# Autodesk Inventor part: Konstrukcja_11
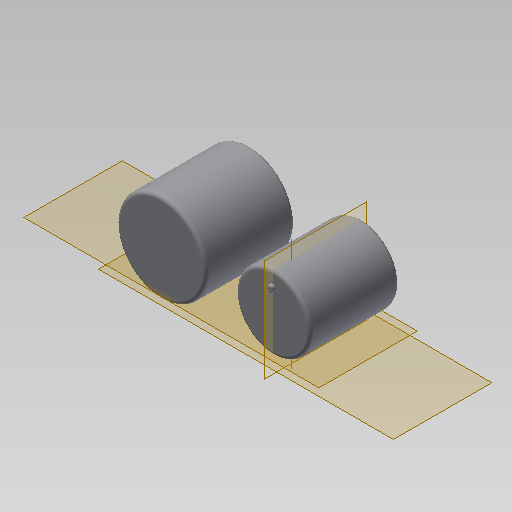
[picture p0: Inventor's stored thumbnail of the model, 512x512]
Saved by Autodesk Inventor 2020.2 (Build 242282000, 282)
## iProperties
Created: 2014-09
Part Number: Konstrukcja_11
Material: Ogólny
Document SubType Name: Modeling
Designer: F.Stasiak
Density: 1 g/cm^3
Appearance: Domyślna
Catalog Web Link: www.expertbooks.pl
Manager: www.cadconsulting.pl
Company: Fabian Stasiak CAD Consulting
Author: F.Stasiak
Subject: Zbiór ćwiczeń. Autodesk Inventor 2020. Kurs Professional
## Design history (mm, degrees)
sketch "Szkic1"
  geometry: L1 (0, 0)-(1500, 0); C1 r 600 at (0, 0); C2 r 500 at (1500, 0); 1 further point
  constraints: 2 centre point, 2 end point, 1 coincident, 1 horizontal
  dimensions: "d0" = 1200 diameter of C1; "d1" = 1000 diameter of C2; "d2" = 1500 distance of L1.start L1.end
extrude "Wyciągnięcie proste1" new body sketch "Szkic1" distance "d3" = 1200; taper "d4" = 0 deg
node "Płaszczyzna konstrukcyjna1"
sketch "Szkic2"
  geometry: C1 r 40 at (0, 350); C2 r 40 at (0, 900); 1 further point
  constraints: 2 centre point, 1 equal radius, 1 vertical alignment
  dimensions: "d5" = 80 diameter of C1; "d6" = 350 distance of point (0, 0) C1.centre; "d9" = 550 distance of C2.centre C1.centre
extrude "Wyciągnięcie proste2" join sketch "Szkic2" stored distance "d7" = 100; taper "d8" = 0 deg
fillet "Zaokrąglenie1" dims "d28" = 50
hole "Otwór1" diameter "d12" = 18.631; stored, may be unused: countersink angle "d16" = 90 deg, drill point angle "d18" = 118 deg; dims "d10" = 10, "d11" = 10, "d13" = 41.91, "d14" = 4, "d15" = 2, "d17" = 120
hole "Otwór2" diameter "d21" = 30.291; stored, may be unused: countersink angle "d25" = 90 deg, drill point angle "d27" = 118 deg; dims "d19" = 10, "d20" = 10, "d22" = 66.498, "d23" = 4, "d24" = 2, "d26" = 150
node "Płaszczyzna konstrukcyjna2"
sketch "Szkic3"
  geometry: L1 (-450, 1200)-(450, 1200) reference; C1 r 40 at (0, 950); 2 further points
  constraints: 1 centre point, 1 midpoint, 1 vertical alignment
  dimensions: "d29" = 80 diameter of C1; "d30" = 250 distance from line of L1 C1.centre
extrude "Wyciągnięcie proste3" join sketch "Szkic3" stored distance "d31" = 100; taper "d32" = 0 deg
hole "Otwór3" diameter "d35" = 18.631; stored, may be unused: countersink angle "d39" = 90 deg, drill point angle "d41" = 118 deg; dims "d33" = 10, "d34" = 10, "d36" = 41.91, "d37" = 4, "d38" = 2, "d40" = 120
sketch "Szkic4"
  geometry: C1 r 40 at (0, 300); C2 r 500 at (0, 0) reference; 1 further point
  constraints: 1 centre point, 1 vertical alignment
  dimensions: "d42" = 80 diameter of C1; "d43" = 300 distance of C1.centre C2.centre
extrude "Wyciągnięcie proste4" join sketch "Szkic4" distance "d44" = 50; taper "d45" = 0 deg
hole "Otwór4" diameter "d48" = 30.291; stored, may be unused: countersink angle "d52" = 90 deg, drill point angle "d54" = 118 deg; dims "d46" = 10, "d47" = 10, "d49" = 66.498, "d50" = 4, "d51" = 2, "d53" = 100
node "Płaszczyzna konstrukcyjna3"
  node "Oś konstrukcyjna1"
node "Bryła1"
other parameters: "d55" = 0
